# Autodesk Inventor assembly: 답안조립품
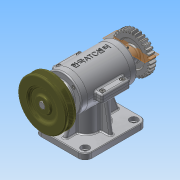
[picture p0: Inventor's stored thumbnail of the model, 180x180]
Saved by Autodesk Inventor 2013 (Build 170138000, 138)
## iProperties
Created: 2015-09
Part Number: 답안조립품
Document SubType Name: Assembly
Designer: Administrator
Mass: 2251.17 g
Surface Area: 1633.51 cm^2
Volume: 528.515 cm^3
Density: 4.25943 g/cm^3
Author: Administrator
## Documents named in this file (17)
- C:\Users\Administrator\Desktop\350908V1027\답안조립품.iam
- C:\Users\Administrator\Desktop\350908V1027\본체.ipt
- C:\Users\Administrator\Desktop\350908V1027\M3x0.5x8.ipt
- C:\Users\Administrator\Desktop\350908V1027\M4x0.5x14.ipt
- C:\Users\Administrator\Desktop\350908V1027\V-벨트풀리.ipt
- C:\Users\Administrator\Desktop\350908V1027\가변스프링.ipt
- C:\Users\Administrator\Desktop\350908V1027\뒤커버.ipt
- C:\Users\Administrator\Desktop\350908V1027\멈춤나사.ipt
- C:\Users\Administrator\Desktop\350908V1027\베어링 6201.ipt
- C:\Users\Administrator\Desktop\350908V1027\베어링 6202.ipt
- C:\Users\Administrator\Desktop\350908V1027\본체 커버.ipt
- C:\Users\Administrator\Desktop\350908V1027\스퍼기어.ipt
- C:\Users\Administrator\Desktop\350908V1027\슬라이드.ipt
- C:\Users\Administrator\Desktop\350908V1027\앞커버.ipt
- C:\Users\Administrator\Desktop\350908V1027\오일실.ipt
- C:\Users\Administrator\Desktop\350908V1027\키4x4.ipt
- C:\Users\Administrator\Desktop\350908V1027\편심축.ipt
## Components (14 placed, 4 different names)
1. M4x0.5x14:1
2. V-벨트풀리:1 — 플러쉬:2, 각도:1
3. 가변스프링:1
4. M4x0.5x14:2
5. M4x0.5x14:3
6. M4x0.5x14:4
7. M3x0.5x8:1
8. M3x0.5x8:3
9. M3x0.5x8:4
10. M3x0.5x8:5
11. M3x0.5x8:2
12. M3x0.5x8:6
13. M3x0.5x8:7
14. M3x0.5x8:8
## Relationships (2: Flush 1, Angle 1)
- 플러쉬:2 [Flush]: V-벨트풀리:1
- 각도:1 [Angle]: V-벨트풀리:1
